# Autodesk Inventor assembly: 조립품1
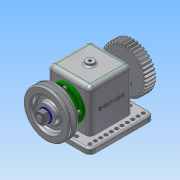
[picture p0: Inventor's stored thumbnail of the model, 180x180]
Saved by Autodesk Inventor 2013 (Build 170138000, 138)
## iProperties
Created: 2018-11
Part Number: 조립품1
Document SubType Name: Assembly
Designer: Administrator
Author: Administrator
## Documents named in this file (13)
- C:\Users\Administrator\Desktop\481107V1008\조립품1.iam
- C:\Users\Administrator\Desktop\481107V1008\본체.ipt
- C:\Users\Administrator\Desktop\481107V1008\V벨트풀리.ipt
- C:\Users\Administrator\Desktop\481107V1008\너트 M12x1.25.ipt
- C:\Users\Administrator\Desktop\481107V1008\베어링 6203.ipt
- C:\Users\Administrator\Desktop\481107V1008\볼트 M4.ipt
- C:\Users\Administrator\Desktop\481107V1008\부시.ipt
- C:\Users\Administrator\Desktop\481107V1008\스퍼기어.ipt
- C:\Users\Administrator\Desktop\481107V1008\오일 실 26 38 8.ipt
- C:\Users\Administrator\Desktop\481107V1008\와셔 12x24.ipt
- C:\Users\Administrator\Desktop\481107V1008\축.ipt
- C:\Users\Administrator\Desktop\481107V1008\커버.ipt
- C:\Users\Administrator\Desktop\481107V1008\키 5x5x12.ipt
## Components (1 placed, 1 different names)
1. V벨트풀리:1
